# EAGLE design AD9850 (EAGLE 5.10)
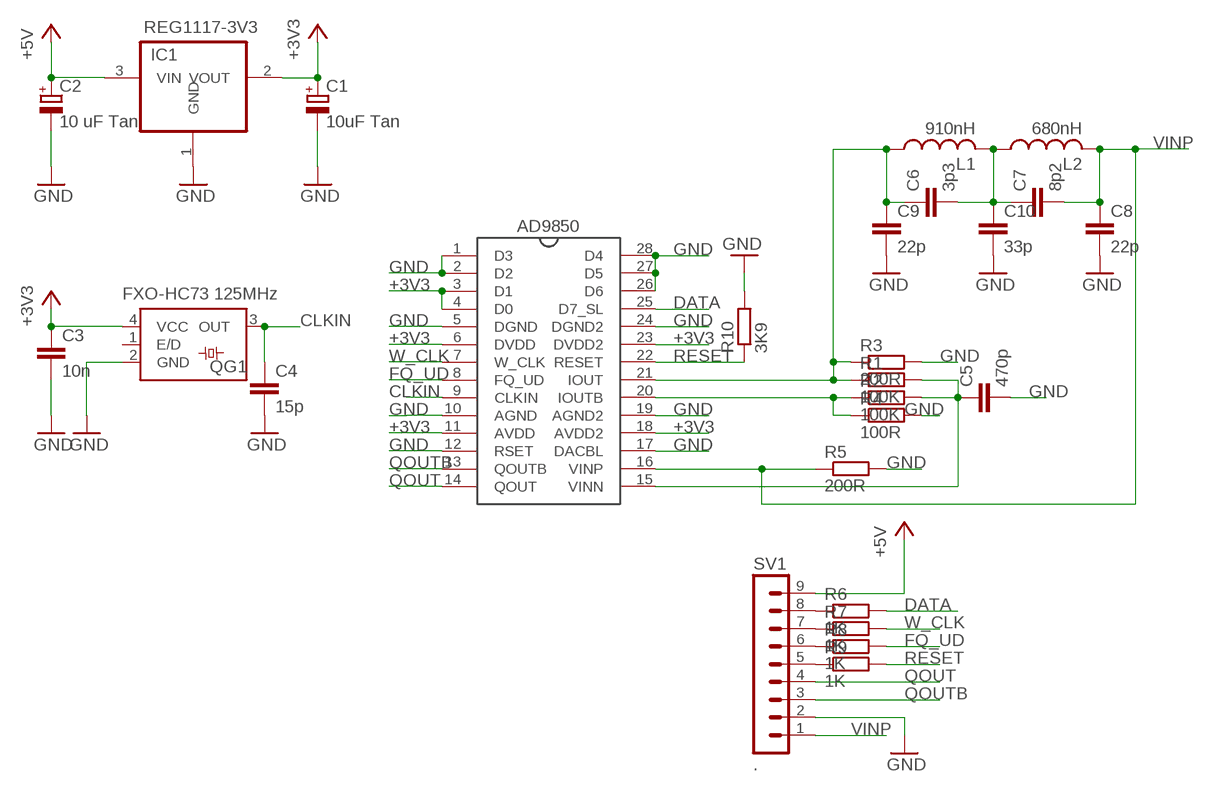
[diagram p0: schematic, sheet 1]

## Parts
C1  10uF Tan  CPOL-EUC/6032-28R  [C/6032-28R]
C2  10 uF Tan  CPOL-EUC/6032-28R  [C/6032-28R]
C3  10n  C-EUC0805K  [C0805K]
C4  15p  C-EUC0805K  [C0805K]
C5  470p  C-EUC0805K  [C0805K]
C6  3p3  C-EUC0805K  [C0805K]
C7  8p2  C-EUC0805K  [C0805K]
C8  22p  C-EUC0805K  [C0805K]
C9  22p  C-EUC0805K  [C0805K]
C10  33p  C-EUC0805K  [C0805K]
IC1  REG1117-3V3  REG1117  [SOT223]
L1  910nH  L-USL1812  [L1812]
L2  680nH  L-USL1812  [L1812]
QG1  FXO-HC73 125MHz  SM77H  [SM77H]
R1  100K  R-EU_M0805  [M0805]
R2  100K  R-EU_M0805  [M0805]
R3  200R  R-EU_M0805  [M0805]
R4  100R  R-EU_M0805  [M0805]
R5  200R  R-EU_M0805  [M0805]
R6  1K  R-EU_M0805  [M0805]
R7  1K  R-EU_M0805  [M0805]
R8  1K  R-EU_M0805  [M0805]
R9  1K  R-EU_M0805  [M0805]
R10  3K9  R-EU_M0805  [M0805]
SV1  .  MA09-1  [MA09-1]
U$1  AD9850  [SSOP28]

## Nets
+3V3: C1.+ C3.1 IC1.2(VOUT) QG1.4(VCC) U$1.3(D1) U$1.4(D0) U$1.6(DVDD) U$1.11(AVDD) U$1.18(AVDD2) U$1.23(DVDD2)
+5V: C2.+ IC1.3(VIN) SV1.9
CLKIN: C4.1 QG1.3(OUT) U$1.9(CLKIN)
DATA: R6.2 U$1.25(D7_SL)
FQ_UD: R8.2 U$1.8(FQ_UD)
GND: C1.- C2.- C3.2 C4.2 C5.2 C8.2 C9.2 C10.2 IC1.1(GND) QG1.2(GND) R3.2 R4.2 R5.2 R10.2 SV1.2 U$1.1(D3) U$1.2(D2) U$1.5(DGND) U$1.10(AGND) U$1.12(RSET) U$1.17(DACBL) U$1.19(AGND2) U$1.24(DGND2) U$1.26(D6) U$1.27(D5) U$1.28(D4)
IOUT: C6.1 C9.1 L1.1 R1.1 R3.1 U$1.21(IOUT)
N$1: R6.1 SV1.8
N$2: R2.1 R4.1 U$1.20(IOUTB)
N$3: R7.1 SV1.7
N$4: C5.1 R1.2 R2.2 U$1.15(VINN)
N$5: R8.1 SV1.6
N$6: R9.1 SV1.5
N$9: C6.2 C7.1 C10.1 L1.2 L2.1
QOUT: SV1.4 U$1.14(QOUT)
QOUTB: SV1.3 U$1.13(QOUTB)
RESET: R9.2 R10.1 U$1.22(RESET)
VINP: C7.2 C8.1 L2.2 R5.1 SV1.1 U$1.16(VINP)
W_CLK: R7.2 U$1.7(W_CLK)
Unconnected: QG1.1(E/D)

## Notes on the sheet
- AD9850

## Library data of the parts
C1 C2 = rcl:CPOL-EU: POLARIZED CAPACITOR, European symbol
C3-C10 = rcl:C-EU: CAPACITOR, European symbol
IC1 = burr-brown:REG1117: 800mA and 1A Low Dropout (LDO) Positive Regulator 1.8V, 2.5V, 2.85V, 3.3V, 5V, and Adj
L1 L2 = rcl:L-US: INDUCTOR, American symbol
QG1 = crystal:SM77H: 3.3V CMOS Clock Oscillator Source: www.pletronics.com .. sm77h%203.3v.pdf
R1-R10 = rcl:R-EU_: RESISTOR, European symbol
SV1 = con-lstb:MA09-1: PIN HEADER
U$1 = ad9850:AD9850: CMOS, 125 MHz Complete DDS Synthesizer

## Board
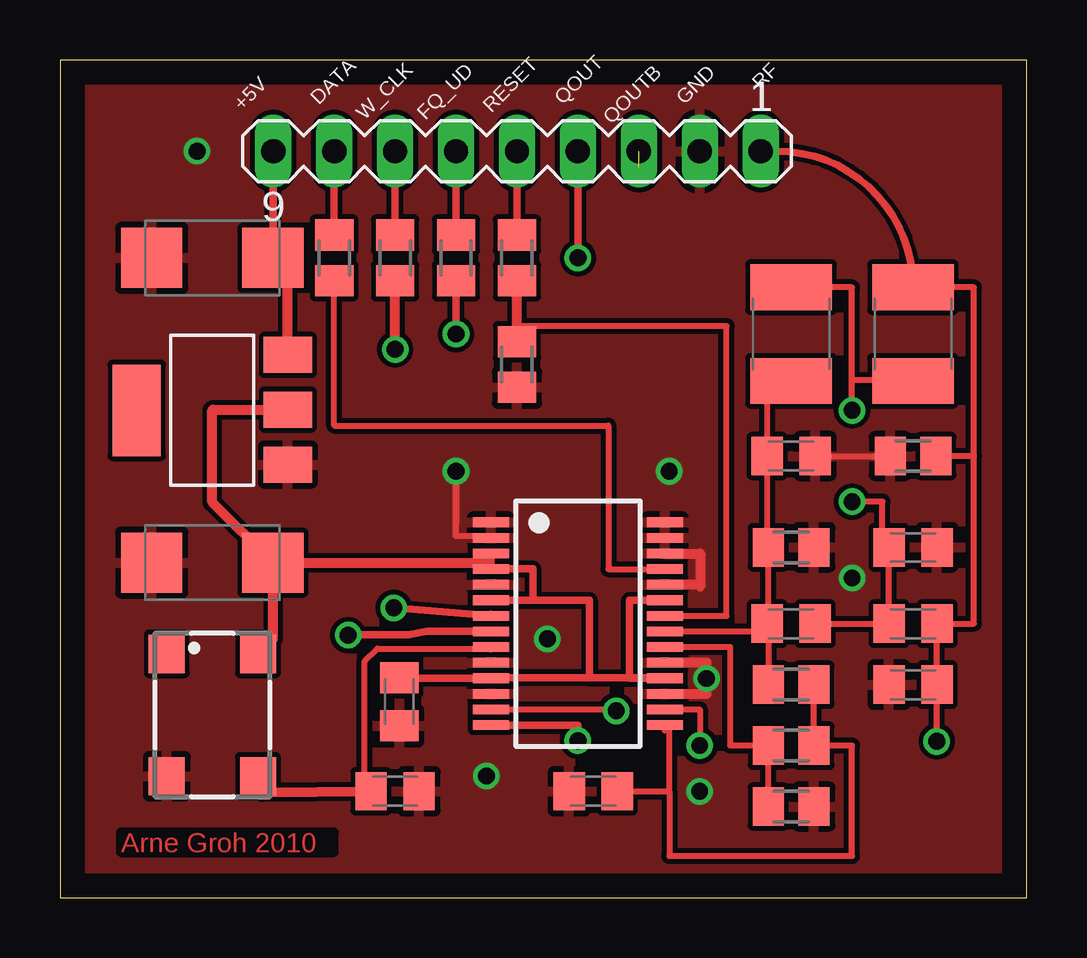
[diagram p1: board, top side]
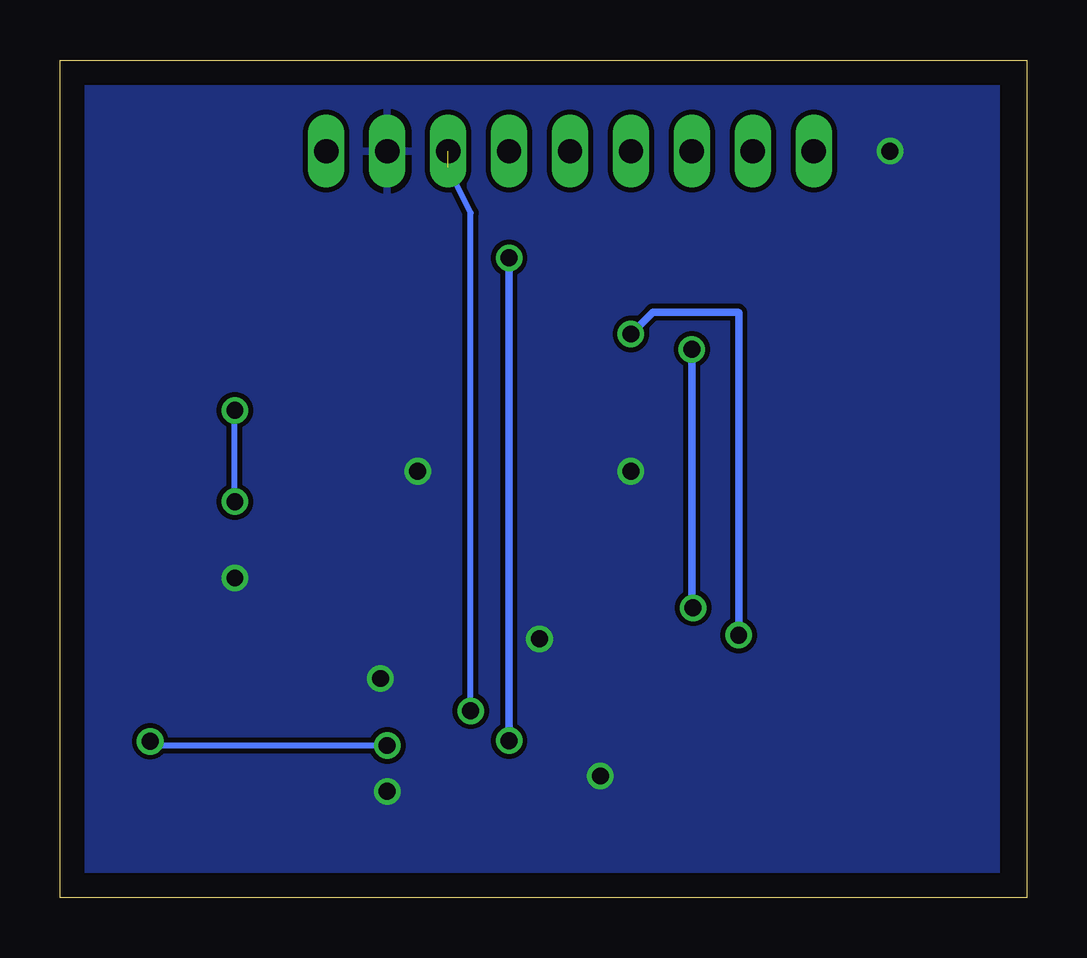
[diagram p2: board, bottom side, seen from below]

Size 40.31 x 34.92 mm. Coordinates in mm from the lower left corner, seen from the top.
Outline: 0,0 40.31,0 40.31,34.92 0,34.92 0,0
Copper layers (1*16): Top 0.035mm / dielectric 1.5mm / Bottom 0.035mm
Design rules "default": minimum track width 10mil, minimum drill 24mil, track to track 8mil, track to pad 8mil, pad to pad 8mil, via to via 8mil, smd to smd 8mil, copper to edge 40mil, drill to drill 8mil, minimum pad ring 10mil, minimum via ring 8mil, stop-mask expansion 4mil, vias tented up to drill 0mil, thermal gap 10mil

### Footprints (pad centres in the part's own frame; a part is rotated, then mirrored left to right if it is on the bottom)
C/6032-28R = smd 2.55 x 2.5: + 2.525,0; - -2.525,0
C0805K = smd 1.3 x 1.6: 1 -1,0; 2 1,0
SOT223 = smd 1.499 x 2.007: 1 -2.261,-3.15; 2 0.025,-3.15; 3 2.311,-3.15 | smd 3.81 x 2.007: 4 0,3.15
L1812 = smd 1.9 x 3.4: 1 -1.95,0; 2 1.95,0
SM77H = smd 1.6 x 1.5: 1 -2.55,-1.9; 2 2.55,-1.9; 3 2.55,1.9; 4 -2.55,1.9
M0805 = smd 1.3 x 1.6: 1 -0.95,0; 2 0.95,0
MA09-1 = drill 1.016 long: 1 -10.16,0; 2 -7.62,0; 3 -5.08,0; 4 -2.54,0; 5 0,0; 6 2.54,0; 7 5.08,0; 8 7.62,0; 9 10.16,0
SSOP28 = smd 0.4 x 1.5: 1 -4.225,-3.625; 2 -3.575,-3.625; 3 -2.925,-3.625; 4 -2.275,-3.625; 5 -1.625,-3.625; 6 -0.975,-3.625; 7 -0.325,-3.625; 8 0.325,-3.625; 9 0.975,-3.625; 10 1.625,-3.625; 11 2.275,-3.625; 12 2.925,-3.625; 13 3.575,-3.625; 14 4.225,-3.625; 15 4.225,3.625; 16 3.575,3.625; 17 2.925,3.625; 18 2.275,3.625; 19 1.625,3.625; 20 0.975,3.625; 21 0.325,3.625; 22 -0.325,3.625; 23 -0.975,3.625; 24 -1.625,3.625; 25 -2.275,3.625; 26 -2.925,3.625; 27 -3.575,3.625; 28 -4.225,3.625

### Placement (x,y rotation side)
C1  6.35,13.97 0 top
C2  6.35,26.67 0 top
C3  14.15,8.18 270 top
C4  13.97,4.45 0 top
C5  22.23,4.45 180 top
C6  30.48,11.43 0 top
C7  35.56,11.43 0 top
C8  35.56,8.89 180 top
C9  30.48,18.42 0 top
C10  35.56,14.61 0 top
IC1  6.35,20.32 90 top
L1  30.48,23.5 90 top
L2  35.56,23.5 90 top
QG1  6.35,7.62 270 top
R1  30.48,8.89 0 top
R2  30.48,6.35 0 top
R3  30.48,14.61 0 top
R4  30.48,3.81 0 top
R5  35.56,18.42 180 top
R6  11.43,26.67 270 top
R7  13.97,26.67 270 top
R8  16.51,26.67 270 top
R9  19.05,26.67 270 top
R10  19.05,22.22 270 top
SV1  19.05,31.11 180 top
U$1  21.59,11.43 270 top

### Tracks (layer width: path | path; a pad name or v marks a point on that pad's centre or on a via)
+3V3
  Top 0.305: 14.17,9.16 U$1.11 17.98,9.17 22.07,9.17 | U$1.3 U$1.4 17.96,13.72 19.71,13.72 19.71,12.41 U$1.6 19.52,12.41 22.07,12.4 22.07,9.17 | 22.07,9.17 23.75,9.17 | 23.75,9.17 U$1.18 23.76,9.16 23.75,9.17 | 23.75,9.17 23.75,12.4 U$1.23
  Top 0.406: IC1.2 6.38,20.34 6.35,20.32 6.35,16.5 C1.+ | C1.+ 8.88,10.8 QG1.4 | C1.+ 17.58,13.97 U$1.3 | 14.17,9.16 C3.1
+5V
  Top 0.305: SV1.9 8.88,31.11 C2.+
  Top 0.406: IC1.3 9.5,26.05 C2.+ 8.89,26.69
CLKIN
  Top 0.254: 17.95,10.44 17.9,10.39 13.23,10.39 12.7,9.86 12.7,4.45
  Top 0.305: C4.1 12.7,4.45
  Top 0.406: QG1.3 8.43,4.41 C4.1 | 17.95,10.44 U$1.9
DATA
  Top 0.254: U$1.25 22.86,13.7 22.86,19.69 11.43,19.69 R6.2
FQ_UD  (via drill 0.7)
  Top 0.305: U$1.8 15.3,11.11 14.53,10.97 12.04,10.97 v12.01,10.95 | v16.51,23.5 R8.2
  Bottom 0.305: v12.01,10.95 12.01,24.38 12.04,24.41 15.6,24.41 v16.51,23.5
GND  (via drill 0.7)
  Top 0.254: C9.2 R5.2 | U$1.10 17.99,9.83 | U$1.2 17.95,14.99 17.84,15.09 16.51,15.09 v16.51,17.78 16.51,15.57
  Top 0.406: U$1.17 26.95,8.51 v26.95,9.14 26.95,9.8 U$1.19 | 26.7,13.05 U$1.24 | 26.7,13.05 26.7,12.98 | 26.7,13.05 26.7,14.35 U$1.26
  other vias: 33.02,13.34 26.67,4.45 20.32,10.8 17.78,5.08 5.71,31.11 25.4,17.78
  pour Top: 1.27,34.29 39.37,34.29 39.37,0.63 1.27,0.63
  pour Bottom: 1.27,34.29 39.37,34.29 39.37,0 1.27,0
IOUT
  Top 0.254: U$1.21 29.48,11.11 | 29.48,11.11 C6.1 29.53,11.43 R3.1 29.48,14.61 C9.1 29.49,21.54 L1.1 | 29.48,11.11 29.53,11.11 R1.1
N$1
  Top 0.305: R6.1 SV1.8
N$2
  Top 0.254: R4.1 R2.1 27.94,6.35 27.94,10.45 U$1.20
N$3
  Top 0.305: R7.1 SV1.7
N$4
  Top 0.254: R1.2 R2.2 33.02,6.35 33.02,1.75 25.4,1.75 25.4,4.45 | 25.4,4.45 25.4,6.98 25.21,6.98 U$1.15 | C5.1 25.4,4.45
N$5
  Top 0.305: R8.1 SV1.6
N$6
  Top 0.305: R9.1 SV1.5
N$9  (via drill 0.7)
  Top 0.254: C6.2 C7.1 C10.1 34.29,14.61 34.29,16.51 v33.02,16.51 | 33.02,21.59 35.56,21.59 L2.1 | L1.2 33.02,25.45 33.02,21.59 | v33.02,20.32 33.02,21.59
  Bottom 0.254: v33.02,16.51 v33.02,20.32
QOUT  (via drill 0.7)
  Top 0.305: U$1.14 21.59,7.2 v21.59,6.55 | v21.59,26.67 SV1.4
  Bottom 0.305: v21.59,6.55 v21.59,26.67
QOUTB  (via drill 0.7)  (1 unrouted)
  Top 0.254: U$1.13 23.19,7.86 v23.19,7.8
  Bottom 0.254: v23.19,7.8 23.19,28.55 24.13,30.45
RESET
  Top 0.254: U$1.22 27.79,11.76 27.79,23.83 19.05,23.83 R10.1
  Top 0.406: R10.1 R9.2
VINP  (via drill 0.7)
  Top 0.254: L2.2 38.1,25.45 38.1,18.42 | 38.1,18.42 R5.1 | 38.1,18.42 38.1,11.43 C7.2 C8.1 v36.56,6.53 v36.55,6.53 | U$1.16 26.67,7.86 v26.67,6.35
  Top 0.305: SV1.1 29.89,31.11 arc-90 L2.2
  Bottom 0.254: v26.67,6.35 36.55,6.35 v36.55,6.53
W_CLK  (via drill 0.7)
  Top 0.305: v13.92,12.09 U$1.7
  Top 0.406: v13.97,22.86 R7.2 | U$1.7
  Bottom 0.305: 13.97,12.01 v13.97,22.86
  Bottom 0.406: v13.92,12.09 13.97,12.01

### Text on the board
Top: Arne Groh 2010
tNames: +5V | DATA | QOUT | GND | RF | W_CLK | FQ_UD | RESET | QOUTB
